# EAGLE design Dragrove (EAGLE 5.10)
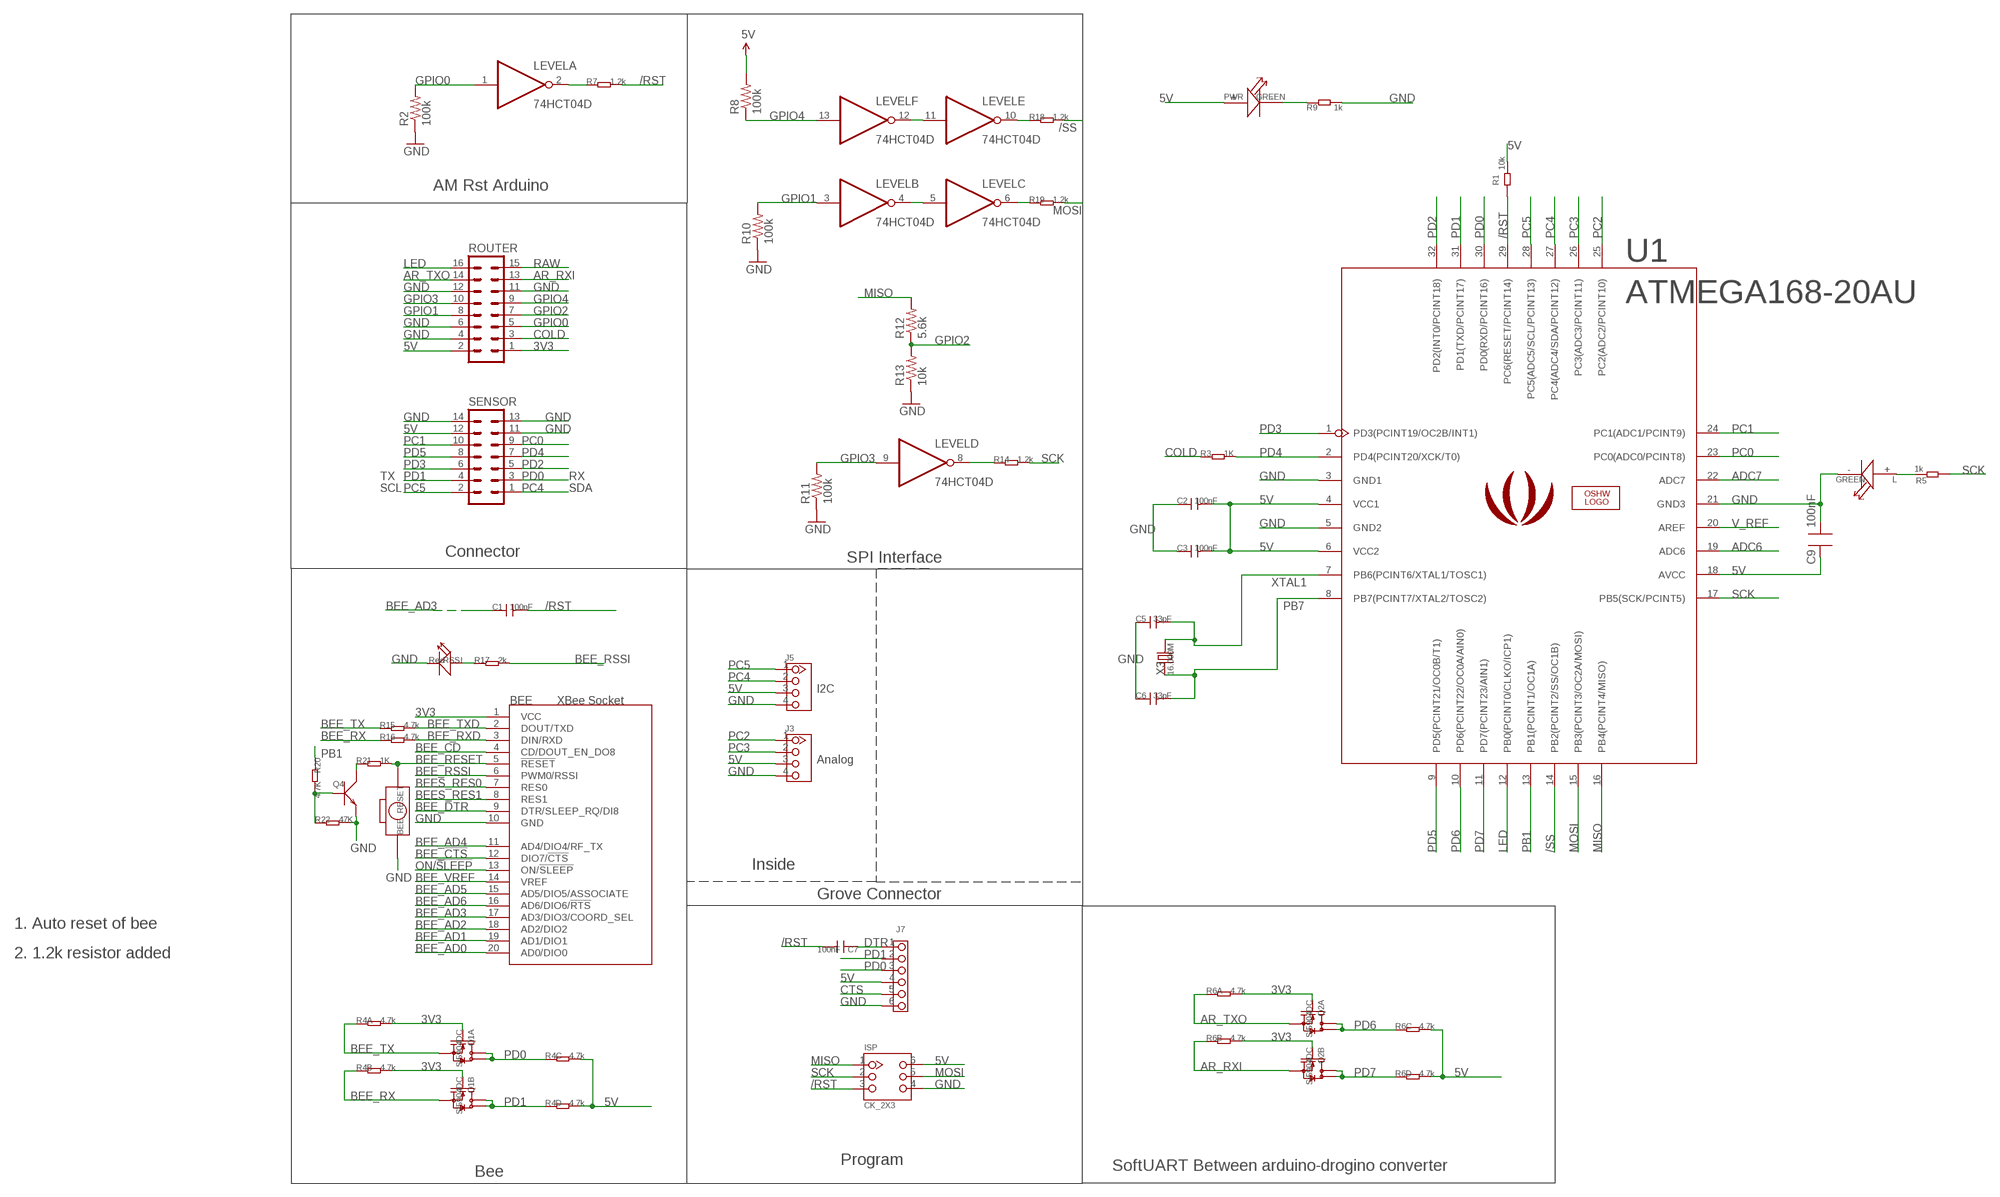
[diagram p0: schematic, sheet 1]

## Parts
BEE  XBee Socket  BEEO  [BEE]
BEE_RESET  3.8x6.1 button  BOTTON_1_SMD  [BOTTON_1]
C1  100nF  C-0603  [0603]
C2  100nF  C-0603  [0603]
C3  100nF  C-0603  [0603]
C5  33pF  C-0603  [0603]
C6  33pF  C-0603  [0603]
C7  100nF  C-0603  [0603]
C9  100nF  C0603  [0603]
ISP  CK_2X3  CK_2X3_DD  [CK_2X3]
J3  TWIG-4P-2.0'90D'  [4P-2.0-90D]
J5  TWIG-4P-2.0'90D'  [4P-2.0-90D]
J7  HEADER-6P-2.54  [6P-2.54]
L  GREEN  LED0805  [LED0805]
LEVEL  74HCT04D  [SO14]
LOGO1  LOGO-OSHW-FILLX0200-NT  [OSHW_FILLX200_NOTEXT]
PWR  GREEN  LED0805  [LED0805]
Q1  Si5904DC  010-DUAL-N-MOSFET_1206-8  [1206-8]
Q2  Si5904DC  010-DUAL-N-MOSFET_1206-8  [1206-8]
Q4  TRANSISTOR-NPN-SOT23''  [SOT23]
R1  10k  R0603  [0603]
R2  100k  RESISTOR0603-RES  [0603-RES]
R3  1K  R-0603  [0603]
R4  4.7k  005-4R_1206  [R1206-8]
R5  1k  R0603  [0603]
R6  4.7k  005-4R_1206  [R1206-8]
R7  1.2k  R-0603  [0603]
R8  100k  RESISTOR0603-RES  [0603-RES]
R9  1k  R0603  [0603]
R10  100k  RESISTOR0603-RES  [0603-RES]
R11  100k  RESISTOR0603-RES  [0603-RES]
R12  5.6k  RESISTOR0603-RES  [0603-RES]
R13  10k  RESISTOR0603-RES  [0603-RES]
R14  1.2k  R-0603  [0603]
R15  4.7k  005-R0603  [0603@1]
R16  4.7k  005-R0603  [0603@1]
R17  2k  005-R0603  [0603@1]
R18  1.2k  R-0603  [0603]
R19  1.2k  R-0603  [0603]
R20  4.7K  005-R0603  [0603@1]
R21  1K  005-R0603  [0603@1]
R22  47K  005-R0603  [0603@1]
ROUTER  MA08-2  [MA08-2]
RSSI  Red  007-LED0603  [D0603]
SENSOR  MA07-2  [MA07-2]
U1  ATMEGA168-20AU  [ATMEGA168-20AU]
U$1  LOGO-SEEEDSTUDIO-SILK  [LOGO_SILK]
X3  16.000M  CRYSTAL-5032  [2P-SMD-5X3.2]

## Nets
3V3: BEE.1(VCC) Q1.2(A:G) Q1.4(B:G) Q2.2(A:G) Q2.4(B:G) R4.7 R4.8 R6.7 R6.8 ROUTER.1
5V: C2.2 C3.2 C9.1 ISP.6 J3.3 J5.3 J7.4 PWR.+ R1.2 R4.5 R4.6 R6.5 R6.6 R8.2 ROUTER.2 SENSOR.12 U1.4(VCC1) U1.6(VCC2) U1.18(AVCC)
/RST: C1.2 C7.2 ISP.3 R1.1 R7.2 U1.29(PC6(RESET/PCINT14))
/SS: R18.2 U1.14(PB2(PCINT2/SS/OC1B))
ADC6: U1.19(ADC6)
ADC7: U1.22(ADC7)
AR_RXI: Q2.3(B:S) R6.2 ROUTER.13
AR_TXO: Q2.1(A:S) R6.1 ROUTER.14
BEE_!CTS: BEE.12(DIO7/!CTS)
BEE_AD0: BEE.20(AD0/DIO0)
BEE_AD1: BEE.19(AD1/DIO1)
BEE_AD2: BEE.18(AD2/DIO2)
BEE_AD3: BEE.17(AD3/DIO3/COORD_SEL) C1.1
BEE_AD4: BEE.11(AD4/DIO4/RF_TX)
BEE_AD5: BEE.15(AD5/DIO5/ASSOCIATE)
BEE_AD6: BEE.16(AD6/DIO6/!RTS)
BEE_CD: BEE.4(CD/DOUT_EN_DO8)
BEE_DTR: BEE.9(DTR/SLEEP_RQ/DI8)
BEE_RESET: BEE.5(!RESET) BEE_RESET.P$2 R21.2
BEE_RSSI: BEE.6(PWM0/RSSI) R17.2
BEE_RX: Q1.3(B:S) R4.2 R16.1
BEE_RXD: BEE.3(DIN/RXD) R16.2
BEE_TX: Q1.1(A:S) R4.1 R15.1
BEE_TXD: BEE.2(DOUT/TXD) R15.2
BEE_VREF: BEE.14(VREF)
BEES_RES0: BEE.7(RES0)
BEES_RES1: BEE.8(RES1)
COLD: R3.1 ROUTER.3
CTS: J7.5
DTR: C7.1 J7.1
GND: BEE.10(GND) BEE_RESET.1 C2.1 C3.1 C5.1 C6.1 C9.2 ISP.4 J3.4 J5.4 J7.6 L.- Q4.2(E) R2.1 R9.2 R10.1 R11.1 R13.1 R22.2 ROUTER.4 ROUTER.6 ROUTER.11 ROUTER.12 RSSI.- SENSOR.11 SENSOR.13 SENSOR.14 U1.3(GND1) U1.5(GND2) U1.21(GND3)
GPIO0: LEVEL.1(A:I) R2.2 ROUTER.5
GPIO1: LEVEL.3(B:I) R10.2 ROUTER.8
GPIO2: R12.1 R13.2 ROUTER.7
GPIO3: LEVEL.9(D:I) R11.2 ROUTER.10
GPIO4: LEVEL.13(F:I) R8.1 ROUTER.9
LED: ROUTER.16 U1.12(PB0(PCINT0/CLKO/ICP1))
MISO: ISP.1 R12.2 U1.16(PB4(PCINT4/MISO))
MOSI: ISP.5 R19.2 U1.15(PB3(PCINT3/OC2A/MOSI))
N$1: LEVEL.8(D:O) R14.1
N$2: LEVEL.2(A:O) R7.1
N$3: PWR.- R9.1
N$4: L.+ R5.2
N$5: LEVEL.10(E:O) R18.1
N$6: R17.1 RSSI.+
N$7: LEVEL.6(C:O) R19.1
N$9: Q4.3(C) R21.1
N$10: LEVEL.11(E:I) LEVEL.12(F:O)
N$11: Q4.1(B) R20.2 R22.1
N$28: LEVEL.4(B:O) LEVEL.5(C:I)
ON/!SLEEP: BEE.13(ON/!SLEEP)
PB1: R20.1 U1.13(PB1(PCINT1/OC1A))
PB7: C6.2 U1.8(PB7(PCINT7/XTAL2/TOSC2)) X3.1
PC0: SENSOR.9 U1.23(PC0(ADC0/PCINT8))
PC1: SENSOR.10 U1.24(PC1(ADC1/PCINT9))
PC2: J3.1 U1.25(PC2(ADC2/PCINT10))
PC3: J3.2 U1.26(PC3(ADC3/PCINT11))
PC4: J5.2 SENSOR.1 U1.27(PC4(ADC4/SDA/PCINT12))
PC5: J5.1 SENSOR.2 U1.28(PC5(ADC5/SCL/PCINT13))
PD0: J7.3 Q1.7(A:D) Q1.8(A:D) R4.3 SENSOR.3 U1.30(PD0(RXD/PCINT16))
PD1: J7.2 Q1.5(B:D) Q1.6(B:D) R4.4 SENSOR.4 U1.31(PD1(TXD/PCINT17))
PD2: SENSOR.5 U1.32(PD2(INT0/PCINT18))
PD3: SENSOR.6 U1.1(PD3(PCINT19/OC2B/INT1))
PD4: R3.2 SENSOR.7 U1.2(PD4(PCINT20/XCK/T0))
PD5: SENSOR.8 U1.9(PD5(PCINT21/OC0B/T1))
PD6: Q2.7(A:D) Q2.8(A:D) R6.3 U1.10(PD6(PCINT22/OC0A/AIN0))
PD7: Q2.5(B:D) Q2.6(B:D) R6.4 U1.11(PD7(PCINT23/AIN1))
RAW: ROUTER.15
SCK: ISP.2 R5.1 R14.2 U1.17(PB5(SCK/PCINT5))
V_REF: U1.20(AREF)
XTAL1: C5.2 U1.7(PB6(PCINT6/XTAL1/TOSC1)) X3.2

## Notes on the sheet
- AM Rst Arduino
- TX | RX
- SCL | SDA
- Connector
- SPI Interface
- I2C
- Analog
- Inside
- Grove Connector
- 1. Auto reset of bee
- 2. 1.2k resistor added
- Program
- SoftUART Between arduino-drogino converter
- Bee

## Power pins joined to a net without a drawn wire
5V: LEVEL.14(P:VCC)
GND: LEVEL.7(P:GND)

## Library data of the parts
BEE = EXT_moudle:BEE
BEE_RESET = CPT_SMD:BOTTON_1
C1-C3 C5-C7 = Discrete:C*: Ceramic Capacitors
C9 = CPT_SMD:C0603; C0603: 100N
ISP = CONNECTER:CK_2X3
J3 J5 = Connector:TWIG-4P-2.0
J7 = Connector:HEADER-6P
L PWR = CPT_SMD:LED0805
LEVEL = 74xx-eu:74*04: Hex INVERTER
LOGO1 = logo:LOGO-OSHW-FILL
Q1 Q2 = Discrete:010-DUAL-N-MOSFET*: Si5902BDC Si5904DC Si5908DC Si5920DC
Q4 = Discreter:TRANSISTOR-NPN*: NPN audion
R1 R5 R9 = CPT_SMD:R0603
R2 R8 R10-R13 = sparkFun:RESISTOR: Resistor
R3 R7 R14 R18 R19 = Discrete:R*
R4 R6 = Discrete:005-4R*: Resistor Array
R15-R17 R20-R22 = Discrete:005-R*
ROUTER = con-lstb:MA08-2: PIN HEADER
RSSI = Discrete:007-LED*
SENSOR = con-lstb:MA07-2: PIN HEADER
U1 = IC_SMD:ATMEGA168-20AU
U$1 = logo:LOGO-SEEEDSTUDIO
X3 = Discrete:CRYSTAL*: CRYSTAL

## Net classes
0 default: width 0.203 mm, drill 0.305 mm, clearance 0.152 mm
3 usbvcc: width 0.203 mm, drill 0.305 mm, clearance 0.203 mm

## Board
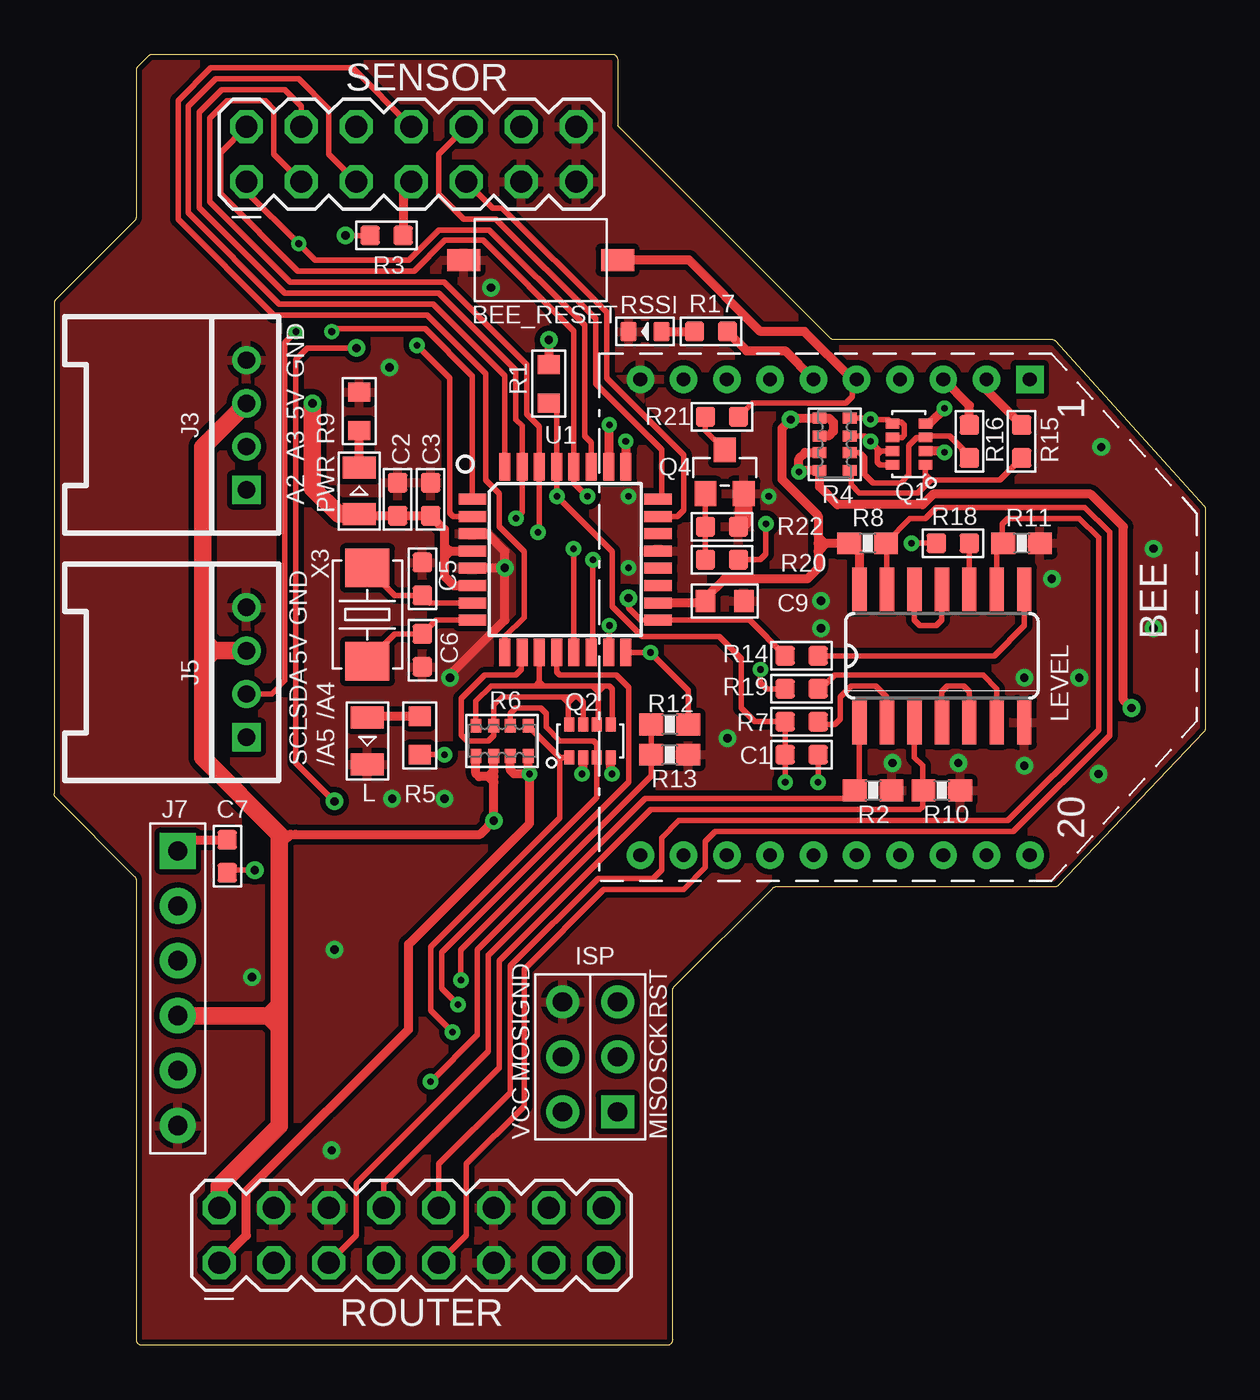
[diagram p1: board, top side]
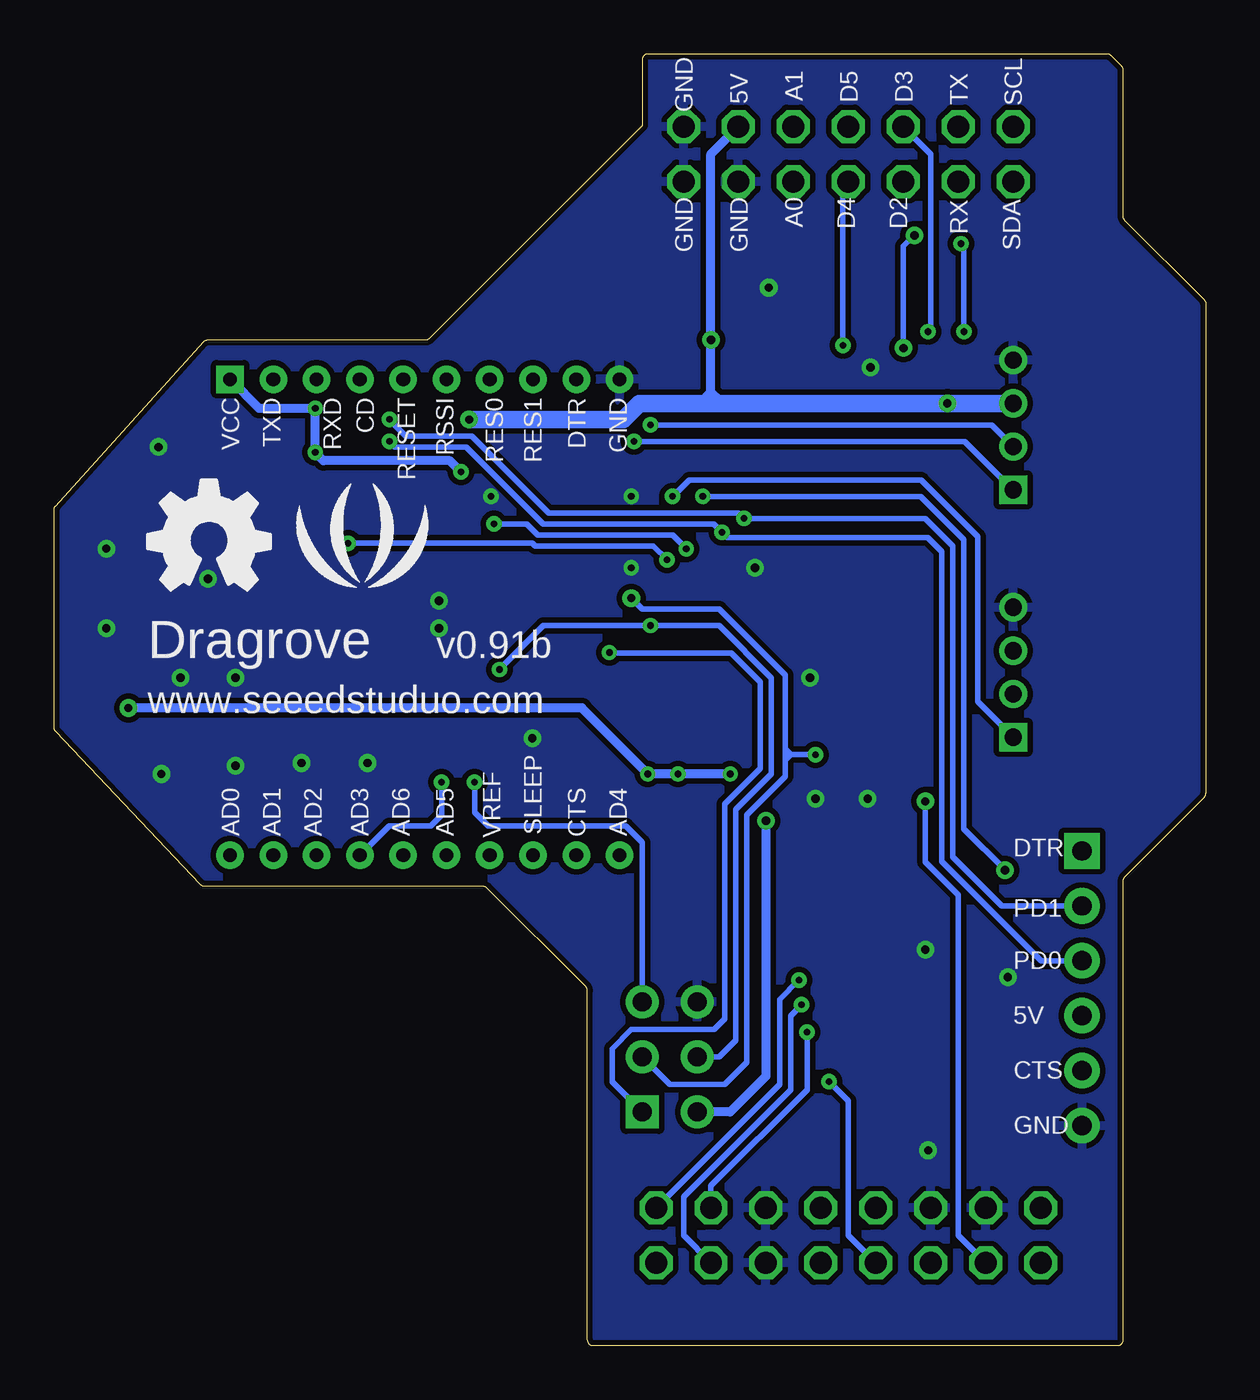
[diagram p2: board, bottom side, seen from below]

Size 53.21 x 59.69 mm. Coordinates in mm from the lower left corner, seen from the top.
Outline: 3.81,54.75 3.81,58.95 arc-45 3.88,59.13 4.37,59.62 arc-45 4.55,59.69 25.78,59.69 arc-90 26.04,59.44 26.04,56.39 35.87,46.56 arc45 36.05,46.48 46.12,46.48 arc-48 46.3,46.4 53.15,38.81 arc-42 53.21,38.64 53.21,28.55 arc-43 53.14,28.38 46.43,21.29 arc-47 46.25,21.21 33.38,21.21 arc45 33.2,21.14 28.65,16.58 arc45 28.57,16.41 28.57,0.25 arc-90 28.32,0 4.06,0 arc-90 3.81,0.25 3.81,21.48 arc45 3.74,21.66 0.07,25.33 arc-45 0,25.5 0,48.16 arc-45 0.07,48.33 3.74,52 arc45 3.81,52.17 3.81,54.74
Copper layers (1*16): Top 0.035mm / dielectric 1.5mm / Bottom 0.035mm
Design rules "default *": minimum track width 10mil, minimum drill 12mil, track to track 8mil, track to pad 8mil, pad to pad 8mil, via to via 8mil, smd to smd 0mil, copper to edge 10mil, drill to drill 8mil, minimum pad ring 10mil, minimum via ring 8mil, stop-mask expansion 4mil, vias tented up to drill 25mil, thermal gap 10mil

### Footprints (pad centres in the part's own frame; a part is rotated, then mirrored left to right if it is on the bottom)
BEE = drill 0.635 pad 1.27 square: 1 -11,0 | drill 0.635 pad 1.27 round: 2 -11,-2; 3 -11,-4; 4 -11,-6; 5 -11,-8; 6 -11,-10; 7 -11,-12; 8 -11,-14; 9 -11,-16; 10 -11,-18; 11 11,-18; 12 11,-16; 13 11,-14; 14 11,-12; 15 11,-10; 16 11,-8; 17 11,-6; 18 11,-4; 19 11,-2; 20 11,0
BOTTON_1 = smd 1.524 x 1.016: 1 -3.556,0; P$2 3.556,0
0603 = smd 0.889 x 0.889: 1 -0.762,0; 2 0.762,0
0603' = smd 0.889 x 1.016: 1 -0.889,0; 2 0.889,0
CK_2X3 = drill 0.889 pad 1.524 square: 1 -1.27,2.54 | drill 0.889 pad 1.524 round: 2 -1.27,0; 3 -1.27,-2.54; 4 1.27,-2.54; 5 1.27,0; 6 1.27,2.54
4P-2.0-90D = drill 0.8 pad 1.27 square: 1 -3,0 | drill 0.8 pad 1.27 round: 2 -1,0; 3 1,0; 4 3,0
6P-2.54 = drill 0.889 pad 1.651 square: 1 0,6.35 | drill 0.889 pad 1.651 round: 2 0,3.81; 3 0,1.27; 4 0,-1.27; 5 0,-3.81; 6 0,-6.35
LED0805 = smd 1.016 x 1.524: + -1.077,0; - 1.077,0
SO14 = smd 0.66 x 2.032: 1 -3.81,-3.073; 2 -2.54,-3.073; 3 -1.27,-3.073; 4 0,-3.073; 5 1.27,-3.073; 6 2.54,-3.073; 7 3.81,-3.073; 8 3.81,3.073; 9 2.54,3.073; 10 1.27,3.073; 11 0,3.073; 12 -1.27,3.073; 13 -2.54,3.073; 14 -3.81,3.073
1206-8 = smd 0.457 x 0.635: 1 -0.953,-0.762; 2 -0.318,-0.762; 3 0.318,-0.762; 4 0.953,-0.762; 5 0.953,0.762; 6 0.318,0.762; 7 -0.318,0.762; 8 -0.953,0.762
SOT23 = smd 1.016 x 1.143: 1 -0.889,-1.016; 2 0.889,-1.016; 3 0,1.016
0603-RES = smd 1.1 x 1: 1 -0.85,0; 2 0.85,0
R1206-8 = smd 0.508 x 0.635: 1 -1.206,-0.699; 2 -0.381,-0.699; 3 0.381,-0.699; 4 1.206,-0.699; 5 1.206,0.699; 6 0.381,0.699; 7 -0.381,0.699; 8 -1.206,0.699
0603@1 = smd 0.889 x 0.889: 1 -0.762,0; 2 0.762,0
MA08-2 = drill 1.016 octagon: 1 -8.89,-1.27; 2 -8.89,1.27; 3 -6.35,-1.27; 4 -6.35,1.27; 5 -3.81,-1.27; 6 -3.81,1.27; 7 -1.27,-1.27; 8 -1.27,1.27; 9 1.27,-1.27; 10 1.27,1.27; 11 3.81,-1.27; 12 3.81,1.27; 13 6.35,-1.27; 14 6.35,1.27; 15 8.89,-1.27; 16 8.89,1.27
D0603 = smd 0.762 x 0.889: + -0.762,0; - 0.762,0
MA07-2 = drill 1.016 octagon: 1 -7.62,-1.27; 2 -7.62,1.27; 3 -5.08,-1.27; 4 -5.08,1.27; 5 -2.54,-1.27; 6 -2.54,1.27; 7 0,-1.27; 8 0,1.27; 9 2.54,-1.27; 10 2.54,1.27; 11 5.08,-1.27; 12 5.08,1.27; 13 7.62,-1.27; 14 7.62,1.27
ATMEGA168-20AU = smd 1.27 x 0.508: 1 -4.293,2.8; 2 -4.293,2; 3 -4.293,1.2; 4 -4.293,0.4; 5 -4.293,-0.4; 6 -4.293,-1.2; 7 -4.293,-2; 8 -4.293,-2.8; 17 4.293,-2.8; 18 4.293,-2; 19 4.293,-1.2; 20 4.293,-0.4; 21 4.293,0.4; 22 4.293,1.2; 23 4.293,2; 24 4.293,2.8 | smd 0.508 x 1.27: 9 -2.8,-4.293; 10 -2,-4.293; 11 -1.2,-4.293; 12 -0.4,-4.293; 13 0.4,-4.293; 14 1.2,-4.293; 15 2,-4.293; 16 2.8,-4.293; 25 2.8,4.293; 26 2,4.293; 27 1.2,4.293; 28 0.4,4.293; 29 -0.4,4.293; 30 -1.2,4.293; 31 -2,4.293; 32 -2.8,4.293
2P-SMD-5X3.2 = smd 1.778 x 2.032: 1 -2.159,0; 2 2.159,0

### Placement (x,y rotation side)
BEE  45.09,33.66 270 top
BEE_RESET  22.48,50.16 0 top
C1  34.54,27.3 180 top
C2  15.88,39.12 270 top
C3  17.4,39.12 270 top
C5  17.02,35.43 270 top
C6  17.02,32.13 90 top
C7  8,22.61 270 top
C9  100nF  [0603']  30.99,34.42 0 top
ISP  24.76,13.34 180 top
J3  8.89,42.55 90 top
J5  8.89,31.11 90 top
J7  5.71,16.51 0 top
L  14.48,27.94 270 top
LEVEL  41.02,31.88 0 top
LOGO1  48.9,34.92 0 bottom
PWR  14.1,39.5 90 top
Q1  39.5,41.66 90 top
Q2  24.76,27.94 0 top
Q4  30.99,40.39 0 top
R1  10k  [0603']  22.86,44.45 90 top
R2  37.85,25.65 180 top
R3  15.37,51.31 0 top
R4  36.07,41.66 90 top
R5  1k  [0603']  16.89,28.19 90 top
R6  20.7,27.94 180 top
R7  34.54,28.83 180 top
R8  37.59,37.08 180 top
R9  1k  [0603']  14.1,43.18 90 top
R10  41.02,25.65 180 top
R11  44.7,37.08 180 top
R12  28.45,28.7 0 top
R13  28.45,27.3 180 top
R14  34.54,31.88 180 top
R15  44.7,41.78 90 top
R16  42.29,41.78 90 top
R17  30.35,46.86 0 top
R18  41.53,37.08 180 top
R19  34.54,30.35 180 top
R20  30.86,36.32 180 top
R21  30.86,42.93 0 top
R22  30.86,37.85 0 top
ROUTER  16.51,5.08 0 top
RSSI  27.3,46.86 180 top
SENSOR  16.51,55.07 0 top
U1  23.62,36.32 0 top
U$1  38.99,36.7 0 bottom
X3  14.48,33.78 90 top

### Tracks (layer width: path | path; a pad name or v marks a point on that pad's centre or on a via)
3V3  (via drill 0.3 pad 0.64, 0.38 pad 0.81)
  Top 0.406: Q2.2 24.45,26.48 v24.38,26.42 | Q2.4 25.72,26.48 v25.78,26.42 | ROUTER.1 8.89,5.08 8.89,7.11 16.38,14.61 16.38,18.54 21.97,24.13 v21.97,26.42 | R6.8 21.91,26.48 v21.97,26.42 | v21.97,26.42 21.26,26.42 21.08,26.6 R6.7 | Q1.2 41.09,41.34 v41.15,41.27 | R4.7 34.7,41.27 34.42,40.99 v34.42,40.39 34.48,40.45 R4.8 35.37,39.69 36.2,38.86 40.13,38.86 40.62,39.35 47.9,39.35 49.4,37.85 49.4,29.84 v49.78,29.46 | Q1.4 40.45,42.61 v41.15,43.31
  Bottom 0.406: v49.78,29.46 28.83,29.46 v25.78,26.42 v24.38,26.42 v21.97,26.42 | v34.42,40.39 34.92,40.89 40.77,40.89 v41.15,41.27 v41.15,43.31 43.74,43.31 BEE.1
5V  (via drill 0.38 pad 0.81)
  Top 0.254: 29.88,34.32 30,34.32 C9.1 | 35.31,37.47 35.69,37.08
  Top 0.406: v22.86,46.48 R1.2 | U1.6 18.47,35.12 18.03,35.56 18.03,36.45 | 18.03,36.7 18.03,36.45 | 18.27,36.72 18.05,36.72 18.03,36.7 | PWR.+ 14.16,38.35 C2.2 C3.2 18.03,37.72 18.03,36.96 | 20.32,26.04 v20.32,24.26 19.69,23.63 11.15,23.63 10.93,23.63 | 20.32,26.04 20.32,26.29 | 20.32,26.54 R6.6 | 20.32,26.29 20.07,26.29 | R4.6 35.78,42.04 36.01,42.26 36.01,42.66 35.81,42.86 R4.5 34.1,42.86 v34.04,42.8 33.62,42.39 33.62,40.04 35.31,38.35 35.31,37.47 35.31,37.08 | 18.03,36.96 18.03,36.7 | 18.27,36.72 18.31,36.72 | 18.03,36.96 18.27,36.72 | 18.31,36.72 U1.4 | 18.31,36.72 18.03,36.45 | 20.07,26.29 19.64,26.29 19.49,26.43 R6.5 | 20.07,26.29 20.32,26.54 | 20.32,26.29 20.32,26.54 | 20.32,26.04 20.07,26.29 | 29.88,34.32 U1.18 | C9.1 30.1,34.54 30.99,35.43 34.8,35.43 35.31,35.94 35.31,36.7 | 35.31,37.08 35.31,36.7 | 35.31,37.08 35.69,37.08 | 35.69,37.08 R8.2 37.21,36.62 LEVEL.14 | 35.69,37.08 35.31,36.7 | 10.41,23.63 10.93,23.63 | 10.93,23.63 10.54,23.24
  Top 0.61: 9.91,15.24 9.91,15.37 10.41,15.88
  Top 0.813: J3.3 6.86,41.51 6.86,32.64 | 6.86,32.64 7.37,32.13 | J5.3 8.87,32.13 7.37,32.13 | v11.94,43.55 11.94,39.62 13.14,38.42 PWR.+ | ROUTER.2 7.62,7.37 10.41,10.15 10.41,15.24 | 6.86,31.62 6.86,27.18 10.41,23.63 10.41,15.24 | 6.86,31.62 6.86,32.64 | 6.86,31.62 7.37,32.13 | 10.41,15.24 9.91,15.24 | 9.91,15.24 J7.4 | 9.91,15.24 10.41,14.73
  Bottom 0.406: SENSOR.12 22.86,55.07 v22.86,46.48 22.86,44.07 | 22.86,44.07 22.86,43.67 22.73,43.55 | ISP.6 21.97,10.79 20.32,12.45 v20.32,24.26 | 22.86,44.07 23.37,43.56 | 22.86,44.07 22.48,43.69
  Bottom 0.813: J3.3 v11.94,43.55 22.73,43.55 26.18,43.55 26.92,42.8 v34.04,42.8
/RST  (via drill 0.3 pad 0.64, 0.38 pad 0.81)
  Top 0.254: R1.1 23.22,43.2 U1.29 23.22,39.26 v23.24,39.24 25.78,36.7 25.78,34.16 27.18,32.77 30.73,32.77 31.75,31.75 31.75,29.46 32.38,28.83 R7.2 C1.2 v33.78,26.04 | C7.2 8.13,21.84 8.26,21.97 v9.27,21.97
  Bottom 0.254: v23.24,39.24 13.16,39.24 11.18,37.26 11.18,23.88 v9.27,21.97 | ISP.3 26.04,23.24 26.8,24 33.15,24 33.78,24.64 v33.78,26.04
/SS  (via drill 0.3 pad 0.64)
  Top 0.254: v39.62,37.08 R18.2 | U1.14 24.89,32.1 v24.89,36.32
  Bottom 0.254: v39.62,37.08 31.11,37.08 30.99,36.96 25.53,36.96 v24.89,36.32
AR_RXI  (via drill 0.3 pad 0.64)
  Top 0.254: R6.2 21.08,29.21 21.34,29.46 22.48,29.46 22.73,29.21 22.73,28.57 23.37,27.94 24.94,27.94 25.08,27.8 Q2.3 25.08,25.34 17.91,18.16 17.91,16.51 v18.67,15.75
  Bottom 0.254: ROUTER.13 24.13,5.08 24.13,6.86 19.18,11.81 19.18,15.24 v18.67,15.75
AR_TXO  (via drill 0.3 pad 0.64)
  Top 0.254: 23.37,27.18 R6.1 | 23.37,27.18 23.49,27.18 | Q2.1 23.62,27.18 23.49,27.18 | 23.37,27.05 23.37,24.38 17.4,18.41 17.4,15.49 v18.41,14.48 | 23.37,27.05 23.37,27.18 | 23.37,27.05 23.49,27.18
  Bottom 0.254: ROUTER.14 22.86,7.37 18.41,11.81 v18.41,14.48
BEE_AD3  (via drill 0.3 pad 0.64)
  Top 0.254: v35.31,26.04 C1.1
  Bottom 0.254: v35.31,26.04 35.31,24.51 35.81,24 37.74,24 BEE.17
BEE_RESET
  Top 0.254: 36.88,44.66 36.88,43.86 36.58,43.56 32.26,43.56 R21.2
  Top 0.406: BEE.5 36.88,44.66 34.67,46.86 32.64,46.86 29.34,50.16 BEE_RESET.P$2
BEE_RSSI
  Top 0.406: BEE.6 33.78,45.97 32,45.97 R17.2
BEE_RX
  Top 0.254: R4.2 37.23,41.27 37.47,41.04 37.47,40.25 37.85,39.87 39.12,39.87 39.5,40.25 39.5,41.6 39.87,41.97 Q1.3 40.32,42.04 41.38,42.04 42.29,41.12 R16.1
BEE_RXD
  Top 0.406: R16.2 42.29,43.45 BEE.3
BEE_TX
  Top 0.254: R4.1 36.83,40.39 36.83,39.78 37.21,39.4 39.88,39.4 | 39.88,39.4 40.26,39.78 40.26,39.88 | 40.39,39.88 40.26,39.88 | 40.26,40.01 40.26,40.26 | 40.26,40.26 Q1.1 | 39.88,39.4 39.91,39.4 40.39,39.88 | 40.26,39.88 40.26,40.01 | 40.26,40.01 40.51,40.01 | 40.51,40.01 43.69,40.01 R15.1 | 40.39,39.88 40.51,40.01 | 40.51,40.01 40.26,40.26
BEE_TXD
  Top 0.406: BEE.2 43.09,44.16 R15.2
COLD  (via drill 0.38 pad 0.81)
  Top 0.254: v13.46,51.31 R3.1 | v13.97,46.1 11.7,46.1 11.18,45.58 11.18,26.92 v12.95,25.15
  Bottom 0.254: v12.95,25.15 12.95,22.35 11.43,20.83 11.43,5.08 ROUTER.3 | v13.97,46.1 13.97,50.8 v13.46,51.31
DTR
  Top 0.406: C7.1 6.22,23.37 J7.1
GND  (via drill 0.3 pad 0.64, 0.38 pad 0.81)
  Top 0.406: U1.3 20.01,37.52 20.83,36.7 v20.83,35.94 | v20.83,35.94 20.83,33.53 18.29,30.99 v18.29,30.86 | U1.5 20.81,35.92 v20.83,35.94
  Top 0.813: Q4.2 31.88,38.1 R22.2
  other vias: 15.49,45.21 20.19,48.9 15.62,25.27 18.03,25.27 12.95,18.29 12.83,9.02 44.83,30.86 41.78,26.92 48.39,41.53 48.26,26.42 31.11,28.07 38.73,26.92 44.83,26.8 46.1,35.43 47.37,30.86 33.02,39.24 50.8,36.83 50.8,33.15 26.54,35.94 35.43,33.15 35.43,34.42 26.54,39.24 9.14,17.02
  pour Top (isolate 0.254): -1.02,62.36 56.26,61.72 56.26,0 -1.02,0
  pour Bottom (isolate 0.254): -1.02,62.36 56.26,61.72 56.26,0 -1.02,0
GPIO0
  Top 0.254: LEVEL.1 37.2,28.81 | ROUTER.5 13.97,5.08 13.97,7.49 20.07,13.59 20.07,18.06 20.09,18.06 27.3,25.27 36.62,25.27 R2.2 37.21,25.87 LEVEL.1 | LEVEL.1 37.19,28.83
GPIO1
  Top 0.254: ROUTER.8 15.24,7.49 20.57,12.83 20.57,17.78 27.56,24.77 40.01,24.77 40.13,24.89 40.13,25.61 R10.2 40.13,25.69 40.13,26.8 39.75,27.18 LEVEL.3
GPIO2  (via drill 0.3 pad 0.64)
  Top 0.254: v17.4,12.19 19.56,14.35 19.56,18.29 27.6,26.33 R13.2 R12.1
  Bottom 0.254: ROUTER.7 16.51,5.08 16.51,11.3 v17.4,12.19
GPIO3
  Top 0.254: ROUTER.10 17.78,8.38 21.08,11.68 21.08,17.54 25.13,21.59 27.69,21.59 28.07,21.97 28.07,23.46 28.86,24.26 44.07,24.26 48.26,28.45 48.26,37.34 47.37,38.23 44.07,38.23 43.82,37.97 43.82,37.12 R11.2 43.56,36.79 LEVEL.9
GPIO4
  Top 0.254: ROUTER.9 19.05,5.08 19.05,8.38 21.72,11.05 21.72,17.39 25.41,21.08 29.08,21.08 30.1,22.1 30.1,23.29 30.56,23.75 44.32,23.75 48.77,28.19 48.77,37.59 47.63,38.73 40.77,38.73 40.26,38.23 39.55,38.23 38.44,37.12 R8.1 38.48,37.05 LEVEL.13
LED  (via drill 0.3 pad 0.64)
  Top 0.254: U1.12 23.22,31.13 23.37,30.99 25.98,30.99 26.55,30.42 26.55,26.04 | 26.55,26.04 18.8,18.29 v18.8,16.89 | 26.55,26.04
  Bottom 0.254: ROUTER.16 19.68,12.06 19.68,16 v18.8,16.89
MISO  (via drill 0.3 pad 0.64)
  Top 0.254: U1.16 v27.56,32.03 27.56,32 29.3,30.27 R12.2
  Bottom 0.254: ISP.1 27.43,12.19 27.43,13.72 26.54,14.61 22.71,14.61 22.22,15.09 22.22,25.02 20.57,26.67 20.57,30.65 21.92,32 27.53,32 v27.56,32.03
MOSI  (via drill 0.3 pad 0.64)
  Top 0.254: v25.65,33.27 25.65,32.06 U1.15 | v32.64,31.24 32.64,30.64 32.92,30.35 R19.2
  Bottom 0.254: ISP.5 22.48,13.34 21.72,14.1 21.72,24.77 20.07,26.42 20.07,30.86 22.48,33.27 v25.65,33.27 30.61,33.27 v32.64,31.24
N$1
  Top 0.254: LEVEL.8 44.83,33.27 43.43,31.88 R14.1
N$2
  Top 0.254: LEVEL.2 38.48,29.97 37.97,30.48 36.83,30.48 36.32,29.97 36.32,28.96 36.07,28.7 35.43,28.7 R7.1
N$3
  Top 0.406: PWR.- R9.1
N$4
  Top 0.406: 14.61,29.08 14.48,29.08 L.+ | R5.2 15.11,29.08 14.61,29.08 | 14.61,29.08 14.48,28.96
N$5
  Top 0.254: LEVEL.10 R18.1
N$6
  Top 0.406: RSSI.+ R17.1
N$7
  Top 0.254: R19.1 35.43,30.35 36.07,30.99 42.93,30.99 43.56,30.35 LEVEL.6
N$9
  Top 0.254: R21.1 30.1,42.29 Q4.3
N$10
  Top 0.254: LEVEL.12 39.75,33.53 40.01,33.27 40.77,33.27 41.02,33.53 LEVEL.11
N$11
  Top 0.254: R20.2 R22.1 Q4.1
N$28
  Top 0.254: LEVEL.4 41.02,30.23 41.28,30.48 42.04,30.48 42.29,30.23 LEVEL.5
PB1  (via drill 0.3 pad 0.64)
  Top 0.254: U1.13 24,32.05 v24,36.83 | R20.1 32.64,36.32 32.89,36.58 v32.89,37.97
  Bottom 0.254: v24,36.83 24.64,37.47 30.86,37.47 31.37,37.97 v32.89,37.97
PB7
  Top 0.254: U1.8 17.65,33.52 C6.2 15.75,32.89 X3.1
PC0
  Top 0.254: U1.23 28.8,38.32 29.08,38.61 29.08,41.15 25.53,44.7 25.53,47.75 20.7,52.58 20.27,52.58 SENSOR.9
PC1
  Top 0.254: U1.24 28.07,39.12 28.07,41.4 25.02,44.45 25.02,47.47 20.42,52.07 18.92,52.07 17.78,53.21 17.78,55.07 SENSOR.10
PC2  (via drill 0.3 pad 0.64)
  Top 0.406: U1.25 v26.42,41.78
  Bottom 0.254: v26.42,41.78 11.13,41.78 J3.1
PC3  (via drill 0.3 pad 0.64)
  Top 0.406: U1.26 25.62,42.51 v25.65,42.55
  Bottom 0.254: v25.65,42.55 9.89,42.55 J3.2
PC4  (via drill 0.3 pad 0.64)
  Top 0.254: SENSOR.1 8.89,53.34 v11.3,50.93 12.07,50.16 16.38,50.16 17.78,51.56 20.11,51.56 24.51,47.16 24.51,42.04 24.82,41.73 U1.27 | 10.92,46.61 v11.18,46.86 10.67,46.35 10.67,30.73 10.05,30.11 J5.2
  Bottom 0.254: v11.3,50.93 11.18,50.8 v11.18,46.86
PC5  (via drill 0.3 pad 0.64)
  Top 0.254: SENSOR.2 7.69,55.14 7.69,53.23 11.27,49.66 16.64,49.66 18.06,51.08 19.83,51.08 24.02,46.89 U1.28 24.02,39.86 v24.64,39.24
  Bottom 0.254: v24.64,39.24 23.88,40.01 13.15,40.01 10.54,37.4 10.54,29.77 J5.1
PD0  (via drill 0.3 pad 0.64)
  Top 0.254: SENSOR.3 10.16,55.07 10.16,57.15 9.78,57.53 8,57.53 7.2,56.73 7.2,52.87 10.92,49.15 18.03,49.15 21.84,45.34 21.84,43.05 22.42,42.48 U1.30 22.42,37.66 v22.35,37.59 | 38.16,41.34 38.04,41.34 | Q1.8 38.16,40.7 38.04,40.83 38.04,41.34 | 38.04,41.34 38.04,41.47 v37.72,41.78 | R4.3 37.47,42.04 v37.72,41.78 | 38.16,41.34 38.19,41.34 | v37.72,41.78 38.16,41.34 | 38.19,41.34 Q1.7 | 38.19,41.34 38.05,41.2
  Bottom 0.254: J7.3 7.61,17.78 12.19,22.36 12.19,36.69 12.84,37.34 22.1,37.34 v22.35,37.59 22.73,37.97 30.61,37.97 34.16,41.53 37.47,41.53 v37.72,41.78
PD1  (via drill 0.3 pad 0.64)
  Top 0.254: SENSOR.4 11.43,57.28 10.67,58.04 7.75,58.04 6.71,57 6.71,52.6 10.67,48.64 17.78,48.64 21.34,45.09 21.34,42.8 21.62,42.51 U1.31 21.62,38.51 v21.34,38.23 | Q1.6 39.18,41.97 39.29,42.08 39.29,42.54 39.15,42.67 38.8,42.67 Q1.5 38.54,42.8 v37.72,42.8 37.66,42.86 R4.4
  Bottom 0.254: J7.2 9.43,20.32 11.68,22.57 11.68,36.96 12.95,38.23 v21.34,38.23 21.59,38.48 30.35,38.48 33.91,42.04 36.96,42.04 v37.72,42.8
PD2
  Top 0.254: SENSOR.5 12.7,55.07 12.7,57.15 11.3,58.55 7.47,58.55 6.2,57.27 6.2,52.35 10.41,48.13 17.53,48.13 20.82,44.84 U1.32
PD3  (via drill 0.3 pad 0.64)
  Top 0.254: U1.1 19.33,44.81 17.14,46.99 12.95,46.99 v12.83,46.86
  Bottom 0.254: v12.83,46.86 12.7,46.99 12.7,55.07 SENSOR.6
PD4  (via drill 0.3 pad 0.64)
  Top 0.254: U1.2 18.45,38.32 18.29,38.48 18.29,44.7 v16.76,46.23
  Top 0.406: R3.2 16.13,53.42 SENSOR.7
  Bottom 0.254: v16.76,46.23 16.76,53.54 SENSOR.7
PD5
  Top 0.254: SENSOR.8 13.79,59.05 7.24,59.05 5.73,57.54 5.73,52.06 10.16,47.62 17.25,47.62 19.94,44.93 19.94,40.01 20.57,39.37 20.57,37.85 21.72,36.7 21.72,33.66 20.83,32.77 U1.9
PD6
  Top 0.254: 23.49,29.97 20.7,29.97 20.32,29.59 R6.3 20.32,28.19 20.07,27.94 19.08,27.94 18.81,28.21 18.81,29.91 19.89,30.99 21.34,30.99 21.59,31.24 21.59,32 U1.10 | 23.49,29.97 23.75,29.72 | Q2.8 23.75,28.77 23.75,29.59 23.75,29.72 | 23.49,29.97 24,29.97 | 24,29.97 24.22,29.97 24.45,29.74 Q2.7 | 23.75,29.72 24,29.97
PD7
  Top 0.254: R6.4 19.49,29.78 20.19,30.48 22.22,30.48 | Q2.5 25.78,28.77 25.78,30.35 25.65,30.48 25.4,30.48 | 22.22,30.48 22.61,30.48 | Q2.6 25.15,28.77 25.15,30.23 | 22.61,30.48 24.89,30.48 | 24.89,30.48 25.15,30.48 | 25.15,30.48 25.4,30.48 | 22.42,30.68 22.42,30.66 22.61,30.48 | 22.42,30.68 U1.11 | 22.22,30.48 22.42,30.68 | 25.15,30.48 25.15,30.23 | 24.89,30.48 25.15,30.23 | 25.15,30.23 25.4,30.48
SCK  (via drill 0.3 pad 0.64, 0.38 pad 0.81)
  Top 0.254: v18.03,27.3 R5.1 | v26.54,34.54 26.54,34.09 27.11,33.52 U1.17 32.14,33.52 R14.2
  Bottom 0.254: ISP.2 24.76,12.06 22.22,12.06 21.21,13.08 21.21,24.51 19.43,26.29 19.43,27.05 | v26.54,34.54 26.04,34.04 22.48,34.04 19.43,30.99 19.43,27.56 | 19.43,27.05 19.43,27.3 | 19.43,27.3 19.43,27.56 | 19.43,27.3 19.18,27.3 | v18.03,27.3 19.05,27.3 19.18,27.3 | 19.18,27.3 19.43,27.56 | 19.43,27.05 19.18,27.3
XTAL1
  Top 0.254: U1.7 17.37,34.32 C5.2 15.75,34.67 X3.2

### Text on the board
tPlace: GND | 5V | A3 | A2 | GND | 5V | SDA | /A4 | SCL | /A5 | GND | RST | SCK | MOSI | VCC | MISO
bPlace: GND | TX | D3 | D5 | A1 | 5V | SCL | RX | D2 | D4 | A0 | GND | GND | SDA | GND | DTR | RES1 | RES0 | RSSI | RESET | CD | RXD | TXD | VCC | v0.91b | Dragrove | www.seeedstuduo.com | SLEEP | VREF | AD4 | CTS | AD5 | AD6 | AD3 | AD2 | AD1 | AD0 | DTR | PD1 | PD0 | 5V | CTS | GND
